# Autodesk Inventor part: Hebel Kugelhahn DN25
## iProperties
Shininess: 64.0
Length Units: 11269
Angle Units: 11279
Time Units: 11290
Mass Units: 11283
Length Display Precision: 3
Angle Display Precision: 2
Compacted: True
Part Number: Hebel Kugelhahn DN25
Document SubType Name: Modeling
Created: 2003-11
Material: Aluminium - 6061
Designer: AG
Manufacturer: Standard
Standards Organization: Custom
Description: Hebel für Kugelhahn
Density: 0.0
Volumn: 0.0
Area: 0.0
PropertySet Name: Model Information
Control State: 0
Master: False
Checked Out: False
Author: AG
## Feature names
1. Drehung1 [Revolution]
2. Extrusion1
3. Extrusion2
4. Spiegeln1 [Mirror]
5. Drehung2 [Revolution]
6. Rundung5 [Fillet]
7. Rundung6 [Fillet]
8. Bohrung1 [Hole]
9. Bohrung2 [Hole]
10. Rundung7 [Fillet]
11. Extrusion4
